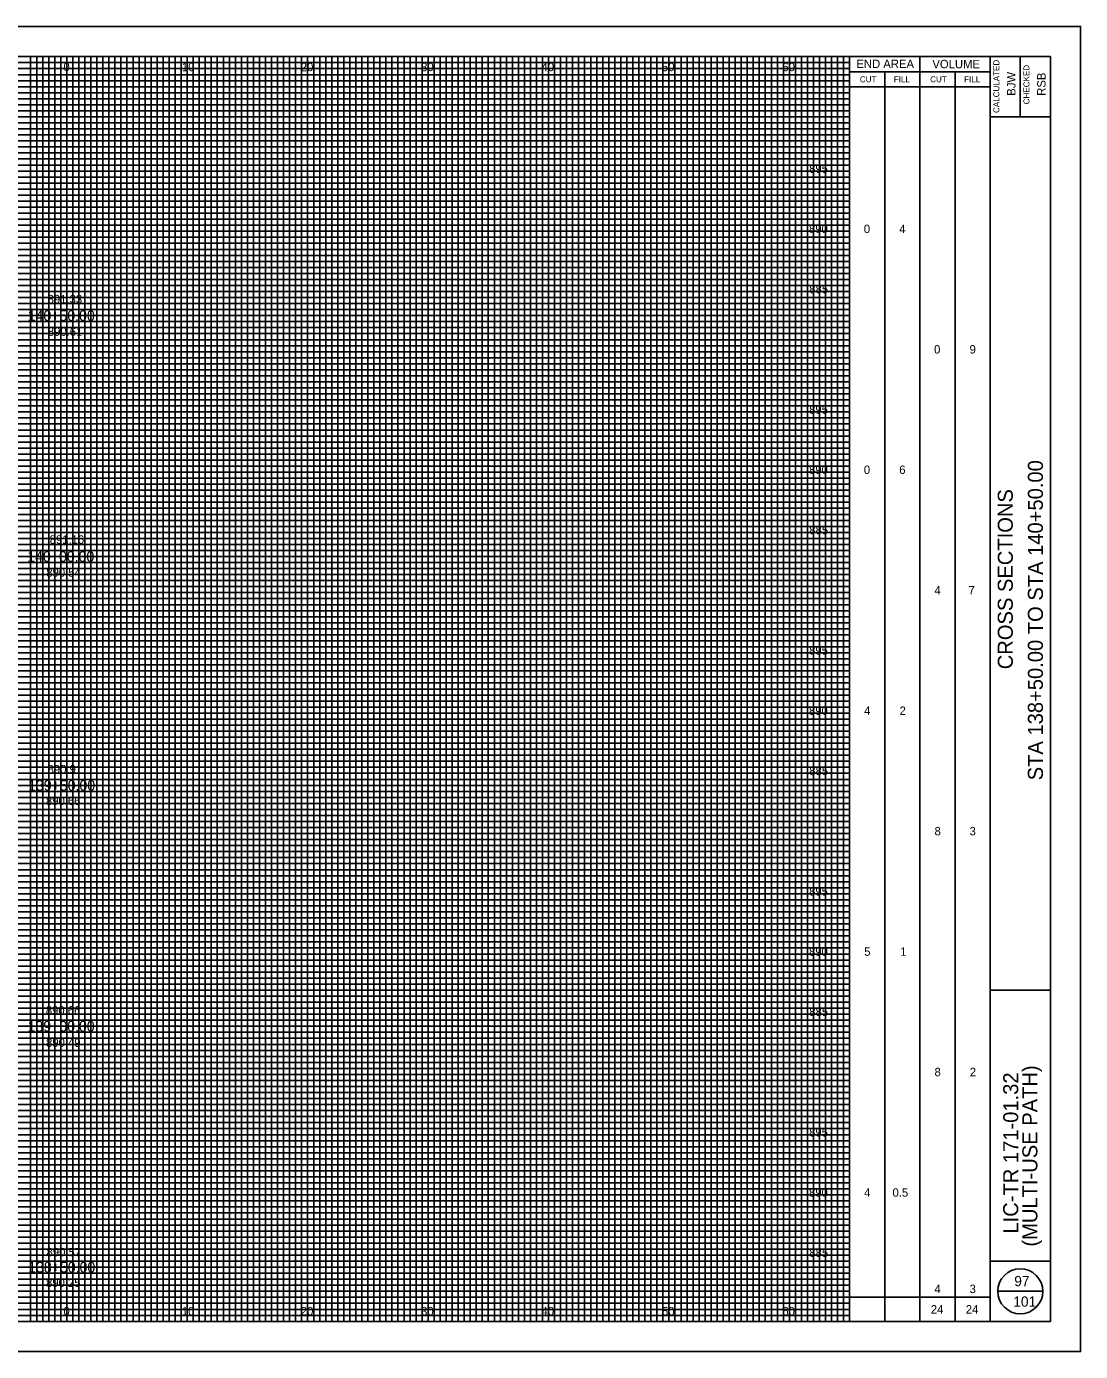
# Model space of a CAD drawing. Extents: x -10 to 160, y -2 to 3672.
# Drawn here: x 72.5 to 160, y 3217.5 to 3327.5 of the extents above; entities that cross this region are included whole.
import ezdxf

# ---------------------------------------------------------------- set-up
doc = ezdxf.new("R2010")
doc.units = 0
for name, color, linetype in [('SH_Border', 7, 'Continuous'), ('SH_Cut_Line', 7, 'Continuous'), ('SH_Data', 7, 'Continuous'), ('SH_Major_Grid_Line', 7, 'Continuous'), ('SH_Minor_Grid_Line', 7, 'Continuous'), ('SH_Text', 7, 'Continuous'), ('TX_P_10', 7, 'Continuous'), ('TX_X_10', 7, 'Continuous')]:
    doc.layers.add(name, color=color, linetype=linetype)

msp = doc.modelspace()

# ---------------------------------------------------------------- linework, layer by layer
at = {"layer": 'SH_Border'}
for p, q in [((152.5, 3220), (152.5, 3325)), ((155, 3325), (155, 3320)), ((152.5, 3320), (157.5, 3320)), ((152.5, 3247.5), (157.5, 3247.5)), ((152.5, 3225), (157.5, 3225))]:
    msp.add_line(p, q, dxfattribs=at)
msp.add_lwpolyline([(0, 3325), (157.5, 3325), (157.5, 3220), (0, 3220)], close=True, dxfattribs=at)
at = {"layer": 'SH_Cut_Line'}
msp.add_lwpolyline([(-10, 3217.5), (160, 3217.5), (160, 3327.5), (-10, 3327.5)], close=True, dxfattribs=at)
at = {"layer": 'SH_Data'}
for p, q in [((140.83, 3220), (140.83, 3325)), ((146.67, 3220), (146.67, 3325)), ((140.83, 3323.75), (152.5, 3323.75)), ((143.75, 3220), (143.75, 3323.75)), ((149.58, 3220), (149.58, 3323.75)), ((140.83, 3322.5), (152.5, 3322.5)), ((140.83, 3222), (152.5, 3222)), ((153.12, 3222.5), (156.88, 3222.5)), ((142.29, 3221), (142.29, 3221)), ((145.21, 3221), (145.21, 3221)), ((148.12, 3221), (148.12, 3221)), ((151.04, 3221), (151.04, 3221))]:
    msp.add_line(p, q, dxfattribs=at)
msp.add_circle((155, 3222.5), 1.87, dxfattribs=at)
at = {"layer": 'SH_Major_Grid_Line'}
for p, q in [((75.83, 3220), (75.83, 3325)), ((80.83, 3220), (80.83, 3325)), ((85.83, 3220), (85.83, 3325)), ((90.83, 3220), (90.83, 3325)), ((95.83, 3220), (95.83, 3325)), ((100.83, 3220), (100.83, 3325)), ((105.83, 3220), (105.83, 3325)), ((110.83, 3220), (110.83, 3325)), ((115.83, 3220), (115.83, 3325)), ((120.83, 3220), (120.83, 3325)), ((125.83, 3220), (125.83, 3325)), ((130.83, 3220), (130.83, 3325)), ((135.83, 3220), (135.83, 3325)), ((5.83, 3320), (140.83, 3320)), ((5.83, 3315), (140.83, 3315)), ((5.83, 3310), (140.83, 3310)), ((5.83, 3305), (140.83, 3305)), ((5.83, 3300), (140.83, 3300)), ((5.83, 3295), (140.83, 3295)), ((5.83, 3290), (140.83, 3290)), ((5.83, 3285), (140.83, 3285)), ((5.83, 3280), (140.83, 3280)), ((5.83, 3275), (140.83, 3275)), ((5.83, 3270), (140.83, 3270)), ((5.83, 3265), (140.83, 3265)), ((5.83, 3260), (140.83, 3260)), ((5.83, 3255), (140.83, 3255)), ((5.83, 3250), (140.83, 3250)), ((5.83, 3245), (140.83, 3245)), ((5.83, 3240), (140.83, 3240)), ((5.83, 3235), (140.83, 3235)), ((5.83, 3230), (140.83, 3230)), ((5.83, 3225), (140.83, 3225))]:
    msp.add_line(p, q, dxfattribs=at)
at = {"layer": 'SH_Minor_Grid_Line'}
for p, q in [((5.83, 3324.5), (140.83, 3324.5)), ((72.83, 3220), (72.83, 3325)), ((73.33, 3220), (73.33, 3325)), ((73.83, 3220), (73.83, 3325)), ((74.33, 3220), (74.33, 3325)), ((74.83, 3220), (74.83, 3325)), ((75.33, 3220), (75.33, 3325)), ((76.33, 3220), (76.33, 3325)), ((76.83, 3220), (76.83, 3325)), ((77.33, 3220), (77.33, 3325)), ((77.83, 3220), (77.83, 3325)), ((78.33, 3220), (78.33, 3325)), ((78.83, 3220), (78.83, 3325)), ((79.33, 3220), (79.33, 3325)), ((79.83, 3220), (79.83, 3325)), ((80.33, 3220), (80.33, 3325)), ((81.33, 3220), (81.33, 3325)), ((81.83, 3220), (81.83, 3325)), ((82.33, 3220), (82.33, 3325)), ((82.83, 3220), (82.83, 3325)), ((83.33, 3220), (83.33, 3325)), ((83.83, 3220), (83.83, 3325)), ((84.33, 3220), (84.33, 3325)), ((84.83, 3220), (84.83, 3325)), ((85.33, 3220), (85.33, 3325)), ((86.33, 3220), (86.33, 3325)), ((86.83, 3220), (86.83, 3325)), ((87.33, 3220), (87.33, 3325)), ((87.83, 3220), (87.83, 3325)), ((88.33, 3220), (88.33, 3325)), ((88.83, 3220), (88.83, 3325)), ((89.33, 3220), (89.33, 3325)), ((89.83, 3220), (89.83, 3325)), ((90.33, 3220), (90.33, 3325)), ((91.33, 3220), (91.33, 3325)), ((91.83, 3220), (91.83, 3325)), ((92.33, 3220), (92.33, 3325)), ((92.83, 3220), (92.83, 3325)), ((93.33, 3220), (93.33, 3325)), ((93.83, 3220), (93.83, 3325)), ((94.33, 3220), (94.33, 3325)), ((94.83, 3220), (94.83, 3325)), ((95.33, 3220), (95.33, 3325)), ((96.33, 3220), (96.33, 3325)), ((96.83, 3220), (96.83, 3325)), ((97.33, 3220), (97.33, 3325)), ((97.83, 3220), (97.83, 3325)), ((98.33, 3220), (98.33, 3325)), ((98.83, 3220), (98.83, 3325)), ((99.33, 3220), (99.33, 3325)), ((99.83, 3220), (99.83, 3325)), ((100.33, 3220), (100.33, 3325)), ((101.33, 3220), (101.33, 3325)), ((101.83, 3220), (101.83, 3325)), ((102.33, 3220), (102.33, 3325)), ((102.83, 3220), (102.83, 3325)), ((103.33, 3220), (103.33, 3325)), ((103.83, 3220), (103.83, 3325)), ((104.33, 3220), (104.33, 3325)), ((104.83, 3220), (104.83, 3325)), ((105.33, 3220), (105.33, 3325)), ((106.33, 3220), (106.33, 3325)), ((106.83, 3220), (106.83, 3325)), ((107.33, 3220), (107.33, 3325)), ((107.83, 3220), (107.83, 3325)), ((108.33, 3220), (108.33, 3325)), ((108.83, 3220), (108.83, 3325)), ((109.33, 3220), (109.33, 3325)), ((109.83, 3220), (109.83, 3325)), ((110.33, 3220), (110.33, 3325)), ((111.33, 3220), (111.33, 3325)), ((111.83, 3220), (111.83, 3325)), ((112.33, 3220), (112.33, 3325)), ((112.83, 3220), (112.83, 3325)), ((113.33, 3220), (113.33, 3325)), ((113.83, 3220), (113.83, 3325)), ((114.33, 3220), (114.33, 3325)), ((114.83, 3220), (114.83, 3325)), ((115.33, 3220), (115.33, 3325)), ((116.33, 3220), (116.33, 3325)), ((116.83, 3220), (116.83, 3325)), ((117.33, 3220), (117.33, 3325)), ((117.83, 3220), (117.83, 3325)), ((118.33, 3220), (118.33, 3325)), ((118.83, 3220), (118.83, 3325)), ((119.33, 3220), (119.33, 3325)), ((119.83, 3220), (119.83, 3325)), ((120.33, 3220), (120.33, 3325)), ((121.33, 3220), (121.33, 3325)), ((121.83, 3220), (121.83, 3325)), ((122.33, 3220), (122.33, 3325)), ((122.83, 3220), (122.83, 3325)), ((123.33, 3220), (123.33, 3325)), ((123.83, 3220), (123.83, 3325)), ((124.33, 3220), (124.33, 3325)), ((124.83, 3220), (124.83, 3325)), ((125.33, 3220), (125.33, 3325)), ((126.33, 3220), (126.33, 3325)), ((126.83, 3220), (126.83, 3325)), ((127.33, 3220), (127.33, 3325)), ((127.83, 3220), (127.83, 3325)), ((128.33, 3220), (128.33, 3325)), ((128.83, 3220), (128.83, 3325)), ((129.33, 3220), (129.33, 3325)), ((129.83, 3220), (129.83, 3325)), ((130.33, 3220), (130.33, 3325)), ((131.33, 3220), (131.33, 3325)), ((131.83, 3220), (131.83, 3325)), ((132.33, 3220), (132.33, 3325)), ((132.83, 3220), (132.83, 3325)), ((133.33, 3220), (133.33, 3325)), ((133.83, 3220), (133.83, 3325)), ((134.33, 3220), (134.33, 3325)), ((134.83, 3220), (134.83, 3325)), ((135.33, 3220), (135.33, 3325)), ((136.33, 3220), (136.33, 3325)), ((136.83, 3220), (136.83, 3325)), ((137.33, 3220), (137.33, 3325)), ((137.83, 3220), (137.83, 3325)), ((138.33, 3220), (138.33, 3325)), ((138.83, 3220), (138.83, 3325)), ((139.33, 3220), (139.33, 3325)), ((139.83, 3220), (139.83, 3325)), ((140.33, 3220), (140.33, 3325)), ((5.83, 3324), (140.83, 3324)), ((5.83, 3323.5), (140.83, 3323.5)), ((5.83, 3323), (140.83, 3323)), ((5.83, 3322.5), (140.83, 3322.5)), ((5.83, 3322), (140.83, 3322)), ((5.83, 3321.5), (140.83, 3321.5)), ((5.83, 3321), (140.83, 3321)), ((5.83, 3320.5), (140.83, 3320.5)), ((5.83, 3319.5), (140.83, 3319.5)), ((5.83, 3319), (140.83, 3319)), ((5.83, 3318.5), (140.83, 3318.5)), ((5.83, 3318), (140.83, 3318)), ((5.83, 3317.5), (140.83, 3317.5)), ((5.83, 3317), (140.83, 3317)), ((5.83, 3316.5), (140.83, 3316.5)), ((5.83, 3316), (140.83, 3316)), ((5.83, 3315.5), (140.83, 3315.5)), ((5.83, 3314.5), (140.83, 3314.5)), ((5.83, 3314), (140.83, 3314)), ((5.83, 3313.5), (140.83, 3313.5)), ((5.83, 3313), (140.83, 3313)), ((5.83, 3312.5), (140.83, 3312.5)), ((5.83, 3312), (140.83, 3312)), ((5.83, 3311.5), (140.83, 3311.5)), ((5.83, 3311), (140.83, 3311)), ((5.83, 3310.5), (140.83, 3310.5)), ((5.83, 3309.5), (140.83, 3309.5)), ((5.83, 3309), (140.83, 3309)), ((5.83, 3308.5), (140.83, 3308.5)), ((5.83, 3308), (140.83, 3308)), ((5.83, 3307.5), (140.83, 3307.5)), ((5.83, 3307), (140.83, 3307)), ((5.83, 3306.5), (140.83, 3306.5)), ((5.83, 3306), (140.83, 3306)), ((5.83, 3305.5), (140.83, 3305.5)), ((5.83, 3304.5), (140.83, 3304.5)), ((5.83, 3304), (140.83, 3304)), ((5.83, 3303.5), (140.83, 3303.5)), ((5.83, 3303), (140.83, 3303)), ((5.83, 3302.5), (140.83, 3302.5)), ((5.83, 3302), (140.83, 3302)), ((5.83, 3301.5), (140.83, 3301.5)), ((5.83, 3301), (140.83, 3301)), ((5.83, 3300.5), (140.83, 3300.5)), ((5.83, 3299.5), (140.83, 3299.5)), ((5.83, 3299), (140.83, 3299)), ((5.83, 3298.5), (140.83, 3298.5)), ((5.83, 3298), (140.83, 3298)), ((5.83, 3297.5), (140.83, 3297.5)), ((5.83, 3297), (140.83, 3297)), ((5.83, 3296.5), (140.83, 3296.5)), ((5.83, 3296), (140.83, 3296)), ((5.83, 3295.5), (140.83, 3295.5)), ((5.83, 3294.5), (140.83, 3294.5)), ((5.83, 3294), (140.83, 3294)), ((5.83, 3293.5), (140.83, 3293.5)), ((5.83, 3293), (140.83, 3293)), ((5.83, 3292.5), (140.83, 3292.5)), ((5.83, 3292), (140.83, 3292)), ((5.83, 3291.5), (140.83, 3291.5)), ((5.83, 3291), (140.83, 3291)), ((5.83, 3290.5), (140.83, 3290.5)), ((5.83, 3289.5), (140.83, 3289.5)), ((5.83, 3289), (140.83, 3289)), ((5.83, 3288.5), (140.83, 3288.5)), ((5.83, 3288), (140.83, 3288)), ((5.83, 3287.5), (140.83, 3287.5)), ((5.83, 3287), (140.83, 3287)), ((5.83, 3286.5), (140.83, 3286.5)), ((5.83, 3286), (140.83, 3286)), ((5.83, 3285.5), (140.83, 3285.5)), ((5.83, 3284.5), (140.83, 3284.5)), ((5.83, 3284), (140.83, 3284)), ((5.83, 3283.5), (140.83, 3283.5)), ((5.83, 3283), (140.83, 3283)), ((5.83, 3282.5), (140.83, 3282.5)), ((5.83, 3282), (140.83, 3282)), ((5.83, 3281.5), (140.83, 3281.5)), ((5.83, 3281), (140.83, 3281)), ((5.83, 3280.5), (140.83, 3280.5)), ((5.83, 3279.5), (140.83, 3279.5)), ((5.83, 3279), (140.83, 3279)), ((5.83, 3278.5), (140.83, 3278.5)), ((5.83, 3278), (140.83, 3278)), ((5.83, 3277.5), (140.83, 3277.5)), ((5.83, 3277), (140.83, 3277)), ((5.83, 3276.5), (140.83, 3276.5)), ((5.83, 3276), (140.83, 3276)), ((5.83, 3275.5), (140.83, 3275.5)), ((5.83, 3274.5), (140.83, 3274.5)), ((5.83, 3274), (140.83, 3274)), ((5.83, 3273.5), (140.83, 3273.5)), ((5.83, 3273), (140.83, 3273)), ((5.83, 3272.5), (140.83, 3272.5)), ((5.83, 3272), (140.83, 3272)), ((5.83, 3271.5), (140.83, 3271.5)), ((5.83, 3271), (140.83, 3271)), ((5.83, 3270.5), (140.83, 3270.5)), ((5.83, 3269.5), (140.83, 3269.5)), ((5.83, 3269), (140.83, 3269)), ((5.83, 3268.5), (140.83, 3268.5)), ((5.83, 3268), (140.83, 3268)), ((5.83, 3267.5), (140.83, 3267.5)), ((5.83, 3267), (140.83, 3267)), ((5.83, 3266.5), (140.83, 3266.5)), ((5.83, 3266), (140.83, 3266)), ((5.83, 3265.5), (140.83, 3265.5)), ((5.83, 3264.5), (140.83, 3264.5)), ((5.83, 3264), (140.83, 3264)), ((5.83, 3263.5), (140.83, 3263.5)), ((5.83, 3263), (140.83, 3263)), ((5.83, 3262.5), (140.83, 3262.5)), ((5.83, 3262), (140.83, 3262)), ((5.83, 3261.5), (140.83, 3261.5)), ((5.83, 3261), (140.83, 3261)), ((5.83, 3260.5), (140.83, 3260.5)), ((5.83, 3259.5), (140.83, 3259.5)), ((5.83, 3259), (140.83, 3259)), ((5.83, 3258.5), (140.83, 3258.5)), ((5.83, 3258), (140.83, 3258)), ((5.83, 3257.5), (140.83, 3257.5)), ((5.83, 3257), (140.83, 3257)), ((5.83, 3256.5), (140.83, 3256.5)), ((5.83, 3256), (140.83, 3256)), ((5.83, 3255.5), (140.83, 3255.5)), ((5.83, 3254.5), (140.83, 3254.5)), ((5.83, 3254), (140.83, 3254)), ((5.83, 3253.5), (140.83, 3253.5)), ((5.83, 3253), (140.83, 3253)), ((5.83, 3252.5), (140.83, 3252.5)), ((5.83, 3252), (140.83, 3252)), ((5.83, 3251.5), (140.83, 3251.5)), ((5.83, 3251), (140.83, 3251)), ((5.83, 3250.5), (140.83, 3250.5)), ((5.83, 3249.5), (140.83, 3249.5)), ((5.83, 3249), (140.83, 3249)), ((5.83, 3248.5), (140.83, 3248.5)), ((5.83, 3248), (140.83, 3248)), ((5.83, 3247.5), (140.83, 3247.5)), ((5.83, 3247), (140.83, 3247)), ((5.83, 3246.5), (140.83, 3246.5)), ((5.83, 3246), (140.83, 3246)), ((5.83, 3245.5), (140.83, 3245.5)), ((5.83, 3244.5), (140.83, 3244.5)), ((5.83, 3244), (140.83, 3244)), ((5.83, 3243.5), (140.83, 3243.5)), ((5.83, 3243), (140.83, 3243)), ((5.83, 3242.5), (140.83, 3242.5)), ((5.83, 3242), (140.83, 3242)), ((5.83, 3241.5), (140.83, 3241.5)), ((5.83, 3241), (140.83, 3241)), ((5.83, 3240.5), (140.83, 3240.5)), ((5.83, 3239.5), (140.83, 3239.5)), ((5.83, 3239), (140.83, 3239)), ((5.83, 3238.5), (140.83, 3238.5)), ((5.83, 3238), (140.83, 3238)), ((5.83, 3237.5), (140.83, 3237.5)), ((5.83, 3237), (140.83, 3237)), ((5.83, 3236.5), (140.83, 3236.5)), ((5.83, 3236), (140.83, 3236)), ((5.83, 3235.5), (140.83, 3235.5)), ((5.83, 3234.5), (140.83, 3234.5)), ((5.83, 3234), (140.83, 3234)), ((5.83, 3233.5), (140.83, 3233.5)), ((5.83, 3233), (140.83, 3233)), ((5.83, 3232.5), (140.83, 3232.5)), ((5.83, 3232), (140.83, 3232)), ((5.83, 3231.5), (140.83, 3231.5)), ((5.83, 3231), (140.83, 3231)), ((5.83, 3230.5), (140.83, 3230.5)), ((5.83, 3229.5), (140.83, 3229.5)), ((5.83, 3229), (140.83, 3229)), ((5.83, 3228.5), (140.83, 3228.5)), ((5.83, 3228), (140.83, 3228)), ((5.83, 3227.5), (140.83, 3227.5)), ((5.83, 3227), (140.83, 3227)), ((5.83, 3226.5), (140.83, 3226.5)), ((5.83, 3226), (140.83, 3226)), ((5.83, 3225.5), (140.83, 3225.5)), ((5.83, 3224.5), (140.83, 3224.5)), ((5.83, 3224), (140.83, 3224)), ((5.83, 3223.5), (140.83, 3223.5)), ((5.83, 3223), (140.83, 3223)), ((5.83, 3222.5), (140.83, 3222.5)), ((5.83, 3222), (140.83, 3222)), ((5.83, 3221.5), (140.83, 3221.5)), ((5.83, 3221), (140.83, 3221)), ((5.83, 3220.5), (140.83, 3220.5))]:
    msp.add_line(p, q, dxfattribs=at)

# ---------------------------------------------------------------- texts
at = {"layer": 'SH_Data'}
for s, height, p in [('END AREA', 0.7, (141.39, 3324.05)), ('VOLUME', 0.7, (147.7, 3324.03)), ('CUT', 0.5, (141.68, 3322.87)), ('FILL', 0.5, (144.5, 3322.87)), ('CUT', 0.5, (147.52, 3322.87)), ('FILL', 0.5, (150.34, 3322.87)), ('97', 0.85, (154.5, 3222.92)), ('101', 0.85, (154.42, 3221.22))]:
    msp.add_text(s, height=height, dxfattribs=at).set_placement(p)
for s, height, p in [('CALCULATED', 0.5, (153.26, 3320.32)), ('CHECKED', 0.5, (155.76, 3321.04)), ('BJW', 0.7, (154.6, 3321.75)), ('RSB', 0.7, (157.1, 3321.75)), ('STA 138+50.00 TO STA 140+50.00', 1.25, (156.88, 3264.92)), ('CROSS SECTIONS', 1.25, (154.38, 3274.14)), ('(MULTI-USE PATH)', 1.25, (156.42, 3226.21)), ('LIC-TR 171-01.32', 1.25, (154.83, 3227.29))]:
    msp.add_text(s, height=height, rotation=90, dxfattribs=at).set_placement(p)
at = {"layer": 'SH_Text'}
for s, height, p in [('0', 0.7, (75.55, 3323.79)), ('10', 0.7, (85.39, 3323.79)), ('20', 0.7, (95.26, 3323.79)), ('30', 0.7, (105.25, 3323.79)), ('40', 0.7, (115.25, 3323.79)), ('50', 0.7, (125.25, 3323.79)), ('60', 0.7, (135.25, 3323.79)), ('895', 0.7, (137.47, 3315.35)), ('890', 0.7, (137.46, 3310.35)), ('0', 0.7, (142.01, 3310.35)), ('4', 0.7, (144.95, 3310.35)), ('885', 0.7, (137.48, 3305.35)), ('140+50.00', 0.875, (72.59, 3303.06)), ('0', 0.7, (147.84, 3300.35)), ('9', 0.7, (150.79, 3300.35)), ('895', 0.7, (137.47, 3295.35)), ('890', 0.7, (137.46, 3290.35)), ('0', 0.7, (142.01, 3290.35)), ('6', 0.7, (144.95, 3290.35)), ('885', 0.7, (137.48, 3285.35)), ('140+00.00', 0.875, (72.55, 3283.06)), ('4', 0.7, (147.87, 3280.35)), ('7', 0.7, (150.7, 3280.35)), ('895', 0.7, (137.47, 3275.35)), ('890', 0.7, (137.46, 3270.35)), ('4', 0.7, (142.03, 3270.35)), ('2', 0.7, (144.98, 3270.35)), ('885', 0.7, (137.48, 3265.35)), ('139+50.00', 0.875, (72.62, 3264.06)), ('8', 0.7, (147.88, 3260.35)), ('3', 0.7, (150.79, 3260.35)), ('895', 0.7, (137.47, 3255.35)), ('890', 0.7, (137.46, 3250.35)), ('5', 0.7, (142.04, 3250.35)), ('1', 0.7, (145.04, 3250.35)), ('885', 0.7, (137.48, 3245.35)), ('139+00.00', 0.875, (72.58, 3244.06)), ('8', 0.7, (147.88, 3240.35)), ('2', 0.7, (150.81, 3240.35)), ('895', 0.7, (137.47, 3235.35)), ('890', 0.7, (137.46, 3230.35)), ('4', 0.7, (142.03, 3230.35)), ('0.5', 0.7, (144.39, 3230.35)), ('885', 0.7, (137.48, 3225.35)), ('138+50.00', 0.875, (72.63, 3224.06)), ('4', 0.7, (147.87, 3222.35)), ('3', 0.7, (150.79, 3222.35)), ('0', 0.7, (75.55, 3220.5)), ('10', 0.7, (85.39, 3220.5)), ('20', 0.7, (95.26, 3220.5)), ('30', 0.7, (105.25, 3220.5)), ('40', 0.7, (115.25, 3220.5)), ('50', 0.7, (125.25, 3220.5)), ('60', 0.7, (135.25, 3220.5)), ('24', 0.7, (147.57, 3220.65)), ('24', 0.7, (150.48, 3220.65))]:
    msp.add_text(s, height=height, dxfattribs=at).set_placement(p)
at = {"layer": 'TX_P_10'}
for s, p in [('891.33', (74.25, 3304.52)), ('891.16', (74.41, 3284.56)), ('890.91', (74.24, 3265.49)), ('890.66', (74.09, 3245.47)), ('890.57', (74.15, 3225.4))]:
    msp.add_text(s, height=0.7, dxfattribs=at).set_placement(p)
at = {"layer": 'TX_X_10'}
for s, p in [('890.61', (74.26, 3301.82)), ('890.54', (74.13, 3281.82)), ('890.66', (74.1, 3262.86)), ('890.49', (74.11, 3242.79)), ('890.25', (74.11, 3222.86))]:
    msp.add_text(s, height=0.7, dxfattribs=at).set_placement(p)

doc.saveas('drawing.dxf')
